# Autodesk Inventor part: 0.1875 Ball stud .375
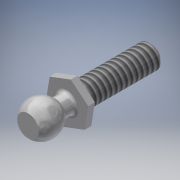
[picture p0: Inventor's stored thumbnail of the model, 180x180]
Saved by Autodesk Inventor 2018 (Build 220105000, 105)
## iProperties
Shininess: 70.0
Length Units: 11272
Angle Units: 11279
Time Units: 11290
Mass Units: 11286
Length Display Precision: 3
Angle Display Precision: 2
Compacted: True
Company: Autodesk
Created: 2000-12
Part Number: 0.1875 Ball stud .375
Document SubType Name: Modeling
Designer: Autodesk, Inc.
Project: Inventor Samples
User Status: IN PROGRESS
Density: 8.08 g/cm^3
Material: Stainless Steel
Mass: 0.939367 g
Surface Area: 1.892 cm^2
Volume: 0.116258 cm^3
Appearance: Steel
Density: 0.0
Volumn: 0.0
Area: 0.0
PropertySet Name: Model Information
Control State: 0
Master: False
Checked Out: False
Author: Autodesk, Inc.
Revision Number: A
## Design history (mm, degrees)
sketch "Sketch3"
  geometry: L1 (-1.183, 7.964)-(-3.755, 6.99); L2 (-3.755, 6.99)-(-4.197, 4.276); L3 (-4.197, 4.276)-(-2.068, 2.536); L4 (-2.068, 2.536)-(0.503, 3.51); L5 (0.503, 3.51)-(0.946, 6.224); L6 (0.946, 6.224)-(-1.183, 7.964); C1 r 2.381 at (-1.626, 5.25)
  constraints: 12 end point, 6 equal length, 6 tangent, 1 centre point, 1 parallel, 1 other
  dimensions: "d2" = 4.7625 diameter of C1
workaxis "Work Axis1"
extrude "Extrusion1" new body sketch "Sketch3" distance "d0" = 0.8128; taper "d1" = 0 deg
sketch "Sketch4"
  geometry: C1 r 1.08 at (-1.626, 5.25); 1 further point
  constraints: 1 centre point, 1 coincident
  dimensions: "d10" = 2.159 diameter of C1
extrude "Extrusion2" join sketch "Sketch4" distance "d11" = 3.175; taper "d12" = 0 deg
sketch "Sketch5"
  geometry: L1 (0, 2.064)-(0, -2.064); C1 r 1.08 at (0, 0) reference; A1 r 2.064 centre (0, 0) between (0, 2.064) and (0, -2.064)
  constraints: 2 end point, 2 point on circle, 1 centre point, 1 coincident, 1 midpoint, 1 vertical
  dimensions: "d13" = 4.1275 diameter of A1
revolve "Revolution1" sketch "Sketch5" stored, may be unused: angle "d14" = 90 deg
fillet "Fillet1" dims "d15" = 0.381
workplane "Work Plane2"
split "Split1"
sketch "Sketch7"
  geometry: C1 r 1.08 at (1.626, 5.25) reference; C2 r 1.422 at (1.626, 5.25)
  constraints: 1 centre point, 1 coincident
  dimensions: "d21" = 2.8448 diameter of C2
extrude "Extrusion3" join sketch "Sketch7" distance "d22" = 9.525; taper "d23" = 0 deg
chamfer "Chamfer1" distance "d24" = 0.381; stored, may be unused: second distance "d25" = 0.381, angle "d28" = 45 deg
thread "Thread1" dims "d26" = 25.4, "d27" = 0
body "Solid1"
other parameters: "d16" = 4.7625
